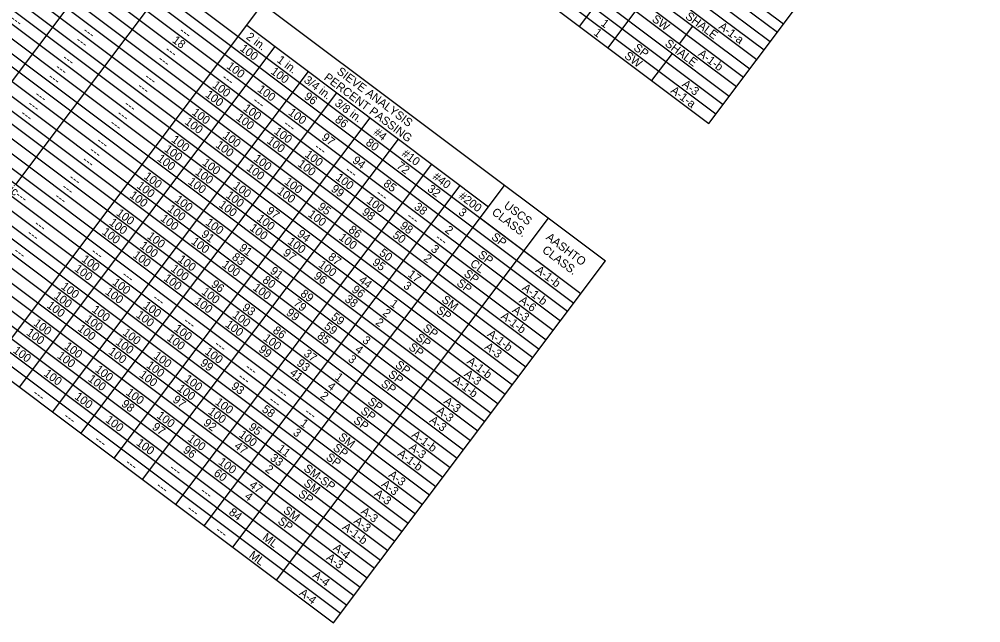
# Model space of a CAD drawing. Extents: x 627484.2 to 627517.5, y 367968.7 to 367996.9.
# Drawn here: x 627511.18 to 627517.5, y 367968.68 to 367972.66 of the extents above; entities that cross this region are included whole.
import ezdxf

# ---------------------------------------------------------------- set-up
doc = ezdxf.new("R2010")
doc.units = 0
doc.layers.add('Default', color=7, linetype='Continuous')

msp = doc.modelspace()

# ---------------------------------------------------------------- linework, layer by layer
at = {"layer": 'Default'}
for p, q in [((627511.7329, 367975.9864), (627516.2081, 367972.6259)), ((627511.6919, 367975.9318), (627516.1671, 367972.5713)), ((627511.645, 367975.8695), (627516.1203, 367972.509)), ((627511.6041, 367975.8149), (627516.0793, 367972.4544)), ((627511.5572, 367975.7525), (627516.0325, 367972.392)), ((627511.5104, 367975.6902), (627515.9856, 367972.3297)), ((627511.4694, 367975.6356), (627515.9446, 367972.2751)), ((627511.4226, 367975.5732), (627515.8978, 367972.2127)), ((627511.3347, 367975.4563), (627515.81, 367972.0958)), ((627511.3757, 367975.5108), (627515.851, 367972.1503)), ((627511.2879, 367975.3939), (627515.7632, 367972.0334)), ((627511.2411, 367975.3315), (627515.7163, 367971.971)), ((627514.8665, 367972.6092), (627516.5497, 367974.8507)), ((627515.0536, 367972.4686), (627516.8422, 367974.8505)), ((627510.5607, 367974.4254), (627515.0359, 367971.0649)), ((627515.7163, 367971.971), (627517.5049, 367974.3529)), ((627510.3997, 367974.211), (627514.8749, 367970.8505)), ((627510.3528, 367974.1486), (627514.8281, 367970.7881)), ((627510.3118, 367974.094), (627514.7871, 367970.7335)), ((627510.265, 367974.0317), (627514.7402, 367970.6712)), ((627510.2182, 367973.9693), (627514.6934, 367970.6088)), ((627510.1713, 367973.9069), (627514.6466, 367970.5464)), ((627510.1245, 367973.8445), (627514.5997, 367970.484)), ((627510.0835, 367973.79), (627514.5588, 367970.4295)), ((627510.0367, 367973.7276), (627514.5119, 367970.3671)), ((627509.9898, 367973.6652), (627514.4651, 367970.3047)), ((627509.9489, 367973.6106), (627514.4241, 367970.2501)), ((627509.902, 367973.5483), (627514.3773, 367970.1878)), ((627509.8552, 367973.4859), (627514.3304, 367970.1254)), ((627509.7674, 367973.3689), (627514.2426, 367970.0084)), ((627509.8083, 367973.4235), (627514.2836, 367970.063)), ((627509.7205, 367973.3066), (627514.1958, 367969.9461)), ((627509.6737, 367973.2442), (627514.1489, 367969.8837)), ((627510.8156, 367971.8259), (627511.9162, 367973.2916)), ((627509.6269, 367973.1818), (627514.1021, 367969.8213)), ((627509.5859, 367973.1273), (627514.0611, 367969.7667)), ((627509.539, 367973.0649), (627514.0143, 367969.7044)), ((627509.4922, 367973.0025), (627513.9674, 367969.642)), ((627511.1586, 367971.5683), (627512.2593, 367973.034)), ((627509.4454, 367972.9401), (627513.9206, 367969.5796)), ((627509.4044, 367972.8856), (627513.8796, 367969.5251)), ((627509.3575, 367972.8232), (627513.8328, 367969.4627)), ((627509.3107, 367972.7608), (627513.786, 367969.4003)), ((627510.9941, 367970.375), (627512.7827, 367972.7568)), ((627509.2639, 367972.6984), (627513.7391, 367969.3379)), ((627509.2229, 367972.6439), (627513.6981, 367969.2834)), ((627512.6773, 367972.6165), (627514.2678, 367971.4222)), ((627515.5236, 367972.4937), (627515.6114, 367972.6107)), ((627509.1761, 367972.5815), (627513.6513, 367969.221)), ((627509.1292, 367972.5191), (627513.6045, 367969.1586)), ((627509.0824, 367972.4567), (627513.5576, 367969.0962)), ((627511.1812, 367970.2345), (627512.8644, 367972.476)), ((627515.3421, 367972.252), (627515.4767, 367972.4313)), ((627509.0414, 367972.4022), (627513.5166, 367969.0417)), ((627508.9946, 367972.3398), (627513.4698, 367968.9793)), ((627511.3995, 367970.0705), (627513.0827, 367972.3121)), ((627508.9477, 367972.2774), (627513.423, 367968.9169)), ((627508.9067, 367972.2228), (627513.382, 367968.8623)), ((627511.5867, 367969.93), (627513.2698, 367972.1716)), ((627508.8189, 367972.1059), (627513.2942, 367968.7454)), ((627508.8599, 367972.1605), (627513.3352, 367968.8)), ((627508.7721, 367972.0435), (627513.2473, 367968.683)), ((627511.805, 367969.7661), (627513.4881, 367972.0076)), ((627511.9921, 367969.6256), (627513.6753, 367971.8671)), ((627512.2104, 367969.4617), (627513.8936, 367971.7032)), ((627512.3975, 367969.3212), (627514.0807, 367971.5627)), ((627512.5846, 367969.1807), (627514.3732, 367971.5625)), ((627512.8731, 367968.964), (627514.6617, 367971.3459)), ((627514.2122, 367971.3481), (627514.8749, 367970.8505)), ((627513.2473, 367968.683), (627515.0359, 367971.0649))]:
    msp.add_line(p, q, dxfattribs=at)

# ---------------------------------------------------------------- texts
for s, p in [('SW', (627515.3378, 367972.6476)), ('SHALE', (627515.5573, 367972.6657)), ('---', (627511.1174, 367972.65)), ('1', (627515.0015, 367972.6197)), ('A-1-a', (627515.7766, 367972.5986)), ('---', (627511.5951, 367972.5717)), ('---', (627512.2289, 367972.5714)), ('2 in.', (627512.6683, 367972.531)), ('1', (627514.9547, 367972.5573)), ('---', (627511.5483, 367972.5094)), ('18', (627512.1826, 367972.5086)), ('100', (627512.6277, 367972.4547)), ('SP', (627515.2166, 367972.4582)), ('SHALE', (627515.4226, 367972.4863)), ('---', (627512.1352, 367972.4466)), ('SW', (627515.1563, 367972.4059)), ('A-1-b', (627515.6412, 367972.4198)), ('---', (627511.4605, 367972.3924)), ('---', (627512.0884, 367972.3842)), ('100', (627512.5399, 367972.3378)), ('1 in.', (627512.871, 367972.3787)), ('---', (627511.4136, 367972.33)), ('100', (627512.8304, 367972.3025)), ('PERCENT PASSING', (627513.1798, 367972.2629)), ('SIEVE ANALYSIS', (627513.2646, 367972.3024)), ('---', (627511.3668, 367972.2677)), ('---', (627512.0005, 367972.2673)), ('100', (627512.4462, 367972.213)), ('---', (627512.5095, 367972.2631)), ('3/4 in.', (627513.0484, 367972.2455)), ('A-3', (627515.5351, 367972.219)), ('---', (627511.279, 367972.1507)), ('---', (627511.9537, 367972.2049)), ('100', (627512.3994, 367972.1507)), ('100', (627512.7426, 367972.1856)), ('96', (627513.0495, 367972.138)), ('A-1-a', (627515.4604, 367972.1775)), ('---', (627511.2321, 367972.0883)), ('---', (627511.8659, 367972.088)), ('---', (627512.7122, 367972.1109)), ('3/8 in.', (627513.2511, 367972.0933)), ('---', (627511.1853, 367972.026)), ('---', (627511.819, 367972.0256)), ('100', (627512.3116, 367972.0337)), ('100', (627512.649, 367972.0608)), ('100', (627512.9453, 367972.0333)), ('---', (627511.7722, 367971.9632)), ('100', (627512.2647, 367971.9713)), ('100', (627512.6021, 367971.9984)), ('---', (627512.9149, 367971.9587)), ('86', (627513.2522, 367971.9858)), ('100', (627512.5143, 367971.8815)), ('100', (627512.8517, 367971.9086)), ('#4', (627513.5062, 367971.9018)), ('---', (627511.6844, 367971.8463)), ('100', (627512.1769, 367971.8544)), ('100', (627512.4675, 367971.8191)), ('100', (627512.8048, 367971.8462)), ('97', (627513.1646, 367971.8687)), ('80', (627513.4548, 367971.8337)), ('---', (627511.6376, 367971.7839)), ('100', (627512.1301, 367971.792)), ('100', (627513.0544, 367971.7564)), ('---', (627513.1176, 367971.8064)), ('#10', (627513.6925, 367971.7619)), ('---Non Plastic---', (627510.7952, 367971.758)), ('---', (627511.5907, 367971.7215)), ('100', (627512.0833, 367971.7297)), ('100', (627512.3796, 367971.7022)), ('100', (627512.717, 367971.7293)), ('100', (627513.0075, 367971.694)), ('94', (627513.367, 367971.7167)), ('72', (627513.6577, 367971.6813)), ('100', (627512.3328, 367971.6398)), ('100', (627512.6702, 367971.6669)), ('---', (627513.3203, 367971.6542)), ('---', (627511.5029, 367971.6046)), ('100', (627511.9954, 367971.6127)), ('100', (627512.286, 367971.5774)), ('100', (627512.9197, 367971.5771)), ('100', (627513.2571, 367971.6042)), ('85', (627513.5707, 367971.5638)), ('#40', (627513.8952, 367971.6097)), ('---', (627511.4561, 367971.5422)), ('100', (627511.9486, 367971.5503)), ('100', (627512.5824, 367971.55)), ('100', (627512.8729, 367971.5147)), ('99', (627513.2267, 367971.5294)), ('32', (627513.8604, 367971.5291)), ('---', (627511.4092, 367971.4798)), ('100', (627511.9018, 367971.488)), ('100', (627512.1982, 367971.4605)), ('100', (627512.5355, 367971.4876)), ('100', (627513.4598, 367971.4519)), ('---', (627513.523, 367971.502)), ('#200', (627514.066, 367971.4814)), ('100', (627512.1513, 367971.3981)), ('100', (627512.4887, 367971.4252)), ('97', (627512.8016, 367971.3853)), ('95', (627513.1397, 367971.4119)), ('98', (627513.4299, 367971.3768)), ('38', (627513.7731, 367971.4117)), ('3', (627514.0652, 367971.3754)), ('CLASS.', (627514.2841, 367971.3758)), ('USCS', (627514.3633, 367971.4195)), ('100', (627511.8139, 367971.371)), ('100', (627512.1045, 367971.3357)), ('100', (627512.7382, 367971.3354)), ('100', (627513.0756, 367971.3625)), ('---', (627513.7257, 367971.3498)), ('---', (627511.2746, 367971.3005)), ('100', (627511.7671, 367971.3086)), ('100', (627512.4009, 367971.3083)), ('100', (627512.6914, 367971.273)), ('86', (627513.3415, 367971.2604)), ('98', (627513.6795, 367971.287)), ('2', (627513.976, 367971.2594)), ('---', (627511.2277, 367971.2381)), ('100', (627511.7203, 367971.2463)), ('100', (627512.0167, 367971.2188)), ('91', (627512.3731, 367971.2316)), ('94', (627513.004, 367971.2334)), ('100', (627513.2783, 367971.2103)), ('50', (627513.6319, 367971.2252)), ('---', (627513.9129, 367971.2093)), ('SP', (627514.2815, 367971.2129)), ('AASHTO', (627514.6404, 367971.2114)), ('100', (627511.9698, 367971.1564)), ('100', (627512.3072, 367971.1835)), ('91', (627512.6226, 367971.1417)), ('100', (627512.9409, 367971.1832)), ('3', (627513.8837, 367971.1337)), ('CLASS.', (627514.6154, 367971.127)), ('---', (627511.1399, 367971.1212)), ('100', (627511.5856, 367971.0669)), ('---', (627511.6489, 367971.117)), ('100', (627511.923, 367971.094)), ('100', (627512.2194, 367971.0666)), ('83', (627512.5745, 367971.0803)), ('97', (627512.9106, 367971.1084)), ('87', (627513.207, 367971.0809)), ('50', (627513.5441, 367971.1082)), ('2', (627513.8355, 367971.0723)), ('SP', (627514.1937, 367971.0959)), ('100', (627511.5388, 367971.0046)), ('100', (627512.1725, 367971.0042)), ('100', (627512.5099, 367971.0313)), ('100', (627513.1437, 367971.0309)), ('95', (627513.4982, 367971.0451)), ('CL', (627514.141, 367971.0379)), ('---', (627511.8516, 367970.9648)), ('100', (627512.1257, 367970.9418)), ('80', (627512.7757, 367970.9293)), ('91', (627512.8254, 367970.9895)), ('96', (627513.1131, 367970.9563)), ('17', (627513.7315, 367970.9675)), ('SP', (627514.1, 367970.9712)), ('A-1-b', (627514.5714, 367970.9952)), ('100', (627511.451, 367970.8876)), ('100', (627511.7883, 367970.9147)), ('96', (627512.4384, 367970.9021)), ('100', (627512.7126, 367970.8791)), ('96', (627513.3627, 367970.8664)), ('44', (627513.4094, 367970.9289)), ('3', (627513.7022, 367970.892)), ('SP', (627514.0532, 367970.9088)), ('A-1-b', (627514.4836, 367970.8782)), ('100', (627511.4041, 367970.8252)), ('100', (627511.7415, 367970.8523)), ('100', (627512.3752, 367970.852)), ('89', (627513.0255, 367970.8392)), ('38', (627513.3165, 367970.8036)), ('100', (627511.3573, 367970.7629)), ('100', (627511.991, 367970.7625)), ('---', (627512.0543, 367970.8126)), ('100', (627512.3284, 367970.7896)), ('93', (627512.6426, 367970.7488)), ('79', (627512.9786, 367970.7769)), ('1', (627513.6156, 367970.7741)), ('SM', (627513.9541, 367970.8003)), ('A-6', (627514.4639, 367970.7955)), ('100', (627511.6537, 367970.7354)), ('100', (627511.9442, 367970.7001)), ('100', (627512.578, 367970.6998)), ('99', (627512.9318, 367970.7145)), ('59', (627513.2282, 367970.687)), ('2', (627513.5662, 367970.7137)), ('SP', (627513.9185, 367970.7295)), ('A-1-b', (627514.3431, 367970.6911)), ('A-3', (627514.4185, 367970.732)), ('100', (627511.2695, 367970.6459)), ('100', (627511.6068, 367970.673)), ('---', (627512.257, 367970.6603)), ('100', (627512.5311, 367970.6374)), ('59', (627513.1813, 367970.6246)), ('2', (627513.5193, 367970.6513)), ('SP', (627513.8307, 367970.6125)), ('100', (627511.2226, 367970.5836)), ('100', (627511.56, 367970.6107)), ('100', (627511.8564, 367970.5832)), ('100', (627512.1938, 367970.6103)), ('86', (627512.8438, 367970.5977)), ('85', (627513.1353, 367970.5617)), ('SP', (627513.7839, 367970.5502)), ('A-1-b', (627514.2553, 367970.5742)), ('100', (627511.4722, 367970.4937)), ('100', (627511.8096, 367970.5208)), ('100', (627512.1469, 367970.5479)), ('---', (627512.4597, 367970.5081)), ('100', (627512.7807, 367970.5475)), ('3', (627513.4329, 367970.5333)), ('SP', (627513.7371, 367970.4878)), ('A-3', (627514.2371, 367970.4903)), ('100', (627511.1348, 367970.4666)), ('100', (627511.4254, 367970.4313)), ('100', (627511.7627, 367970.4584)), ('100', (627512.0591, 367970.431)), ('100', (627512.3965, 367970.4581)), ('99', (627512.7503, 367970.4728)), ('37', (627513.0468, 367970.4453)), ('4', (627513.3844, 367970.4721)), ('100', (627512.0123, 367970.3686)), ('99', (627512.3661, 367970.3833)), ('93', (627513.0012, 367970.382)), ('3', (627513.3392, 367970.4086)), ('SP', (627513.6492, 367970.3709)), ('A-1-b', (627514.1206, 367970.3949)), ('100', (627511.3375, 367970.3144)), ('100', (627511.6749, 367970.3415)), ('100', (627511.9654, 367970.3062)), ('---', (627512.6624, 367970.3559)), ('41', (627512.9556, 367970.3186)), ('SP', (627513.6024, 367970.3085)), ('A-3', (627514.1024, 367970.311)), ('100', (627511.6281, 367970.2791)), ('100', (627512.2618, 367970.2787)), ('---', (627512.6156, 367970.2935)), ('1', (627513.2527, 367970.2907)), ('SP', (627513.5556, 367970.2461)), ('A-1-b', (627514.027, 367970.2701)), ('100', (627511.8776, 367970.1893)), ('100', (627512.215, 367970.2164)), ('93', (627512.5701, 367970.2301)), ('---', (627512.8651, 367970.2037)), ('4', (627513.203, 367970.2304)), ('---', (627511.2661, 367970.1851)), ('100', (627511.5402, 367970.1622)), ('98', (627511.8477, 367970.1142)), ('97', (627512.1847, 367970.1416)), ('100', (627512.4645, 367970.1265)), ('---', (627512.8183, 367970.1413)), ('2', (627513.1564, 367970.1679)), ('SP', (627513.4677, 367970.1292)), ('A-3', (627513.9678, 367970.1317)), ('100', (627512.4177, 367970.0642)), ('58', (627512.772, 367970.0785)), ('---', (627513.0523, 367970.0632)), ('SP', (627513.4209, 367970.0668)), ('A-3', (627513.9209, 367970.0693)), ('---', (627511.4688, 367970.0329)), ('100', (627511.743, 367970.0099)), ('100', (627512.0803, 367970.0371)), ('92', (627512.3873, 367969.9894)), ('1', (627513.0243, 367969.9866)), ('SP', (627513.3741, 367970.0044)), ('A-3', (627513.8741, 367970.0069)), ('97', (627512.05, 367969.9623)), ('95', (627512.6845, 367969.9614)), ('3', (627512.9762, 367969.9252)), ('---', (627511.6715, 367969.8807)), ('100', (627511.9457, 367969.8577)), ('100', (627512.283, 367969.8848)), ('100', (627512.6204, 367969.9119)), ('SM', (627513.275, 367969.8959)), ('A-1-b', (627513.7576, 367969.9115)), ('96', (627512.2525, 367969.8102)), ('47', (627512.5901, 367969.8371)), ('11', (627512.8734, 367969.8195)), ('SP', (627513.2394, 367969.8251)), ('A-3', (627513.7394, 367969.8276)), ('100', (627512.4857, 367969.7326)), ('33', (627512.8253, 367969.7581)), ('SP', (627513.1926, 367969.7627)), ('A-1-b', (627513.664, 367969.7867)), ('---', (627511.8743, 367969.7285)), ('---', (627512.1648, 367969.6932)), ('2', (627512.7934, 367969.6845)), ('SM-SP', (627513.047, 367969.6891)), ('60', (627512.4552, 367969.658)), ('A-3', (627513.6048, 367969.6483)), ('---', (627512.077, 367969.5762)), ('47', (627512.6894, 367969.5797)), ('SM', (627513.0466, 367969.5919)), ('A-3', (627513.5579, 367969.5859)), ('---', (627512.3675, 367969.541)), ('4', (627512.6585, 367969.5054)), ('SP', (627513.0111, 367969.521)), ('A-3', (627513.5111, 367969.5235)), ('SM', (627512.912, 367969.4125)), ('---', (627512.2797, 367969.424)), ('84', (627512.5544, 367969.4006)), ('A-3', (627513.4233, 367969.4066)), ('SP', (627512.8764, 367969.3417)), ('A-1-b', (627513.301, 367969.3033)), ('A-3', (627513.3764, 367969.3442)), ('---', (627512.4668, 367969.2835)), ('ML', (627512.7756, 367969.2346)), ('A-4', (627513.2402, 367969.1661)), ('ML', (627512.6877, 367969.1176)), ('A-3', (627513.195, 367969.1025)), ('A-4', (627513.1056, 367968.9868)), ('A-4', (627513.0177, 367968.8698))]:
    msp.add_text(s, height=0.055, rotation=323.09678, dxfattribs=at).set_placement(p)

doc.saveas('drawing.dxf')
